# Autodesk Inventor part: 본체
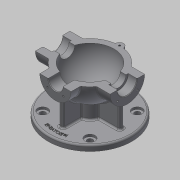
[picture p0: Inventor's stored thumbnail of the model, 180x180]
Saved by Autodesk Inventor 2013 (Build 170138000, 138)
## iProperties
Created: 2015-12
Part Number: 본체
Material: 일반
Document SubType Name: Modeling
Designer: mduedu
Density: 1 g/cm^3
Mass: 407.074 g
Surface Area: 905.391 cm^2
Volume: 407.074 cm^3
Author: mduedu
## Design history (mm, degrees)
sketch "스케치1"
  geometry: L1 (-53, 0)-(53, 0); A1 r 53 centre (0, 0) between (53, 0) and (-53, 0); 2 further points
  constraints: 2 coincident, 2 end point, 2 point on circle, 1 centre point, 1 horizontal, 1 midpoint
  dimensions: "d0" = 53 radius of A1
revolve "회전1" sketch "스케치1" stored, may be unused: angle "d2" = 90 deg
feature "쉘1" dims "d11" = 10
node "작업 평면1"
sketch "스케치2"
  geometry: C1 r 31 at (0, 0); 1 further point
  constraints: 1 centre point, 1 coincident
  dimensions: "d4" = 62 diameter of C1
extrude "돌출1" join sketch "스케치2" stored distance "d5" = 10; taper "d6" = 0 deg
node "작업 평면2"
sketch "스케치3"
  geometry: C1 r 28 at (0, 0); 1 further point
  constraints: 1 centre point, 1 coincident
  dimensions: "d8" = 56 diameter of C1
extrude "돌출2" join sketch "스케치3" stored distance "d9" = 10; taper "d10" = 0 deg
hole "구멍1" diameter "d14" = 35; stored, may be unused: countersink angle "d18" = 90 deg, drill point angle "d20" = 0 deg; dims "d12" = 10, "d13" = 10, "d15" = 6, "d16" = 4, "d17" = 2, "d19" = 16
hole "구멍2" diameter "d23" = 27; stored, may be unused: countersink angle "d27" = 90 deg, drill point angle "d29" = 0 deg; dims "d21" = 10, "d22" = 10, "d24" = 6, "d25" = 4, "d26" = 2, "d28" = 16
fillet "모깎기1" dims "d30" = 0.3
hole "구멍3" diameter "d33" = 26; stored, may be unused: countersink angle "d37" = 90 deg, drill point angle "d39" = 0 deg; dims "d31" = 10, "d32" = 10, "d34" = 6, "d35" = 4, "d36" = 2, "d38" = 16
chamfer "모따기1" distance "d40" = 1; stored, may be unused: second distance "d41" = 2, angle "d42" = 45 deg
sketch "스케치4"
  geometry: L1 (0, 0)-(0, -25); L2 (0, 0)-(-17.678, -17.678); A1 r 25 centre (0, 0) between (-17.678, -17.678) and (0, -25); 1 further point
  constraints: 4 end point, 2 point on circle, 1 centre point, 1 coincident, 1 vertical
  dimensions: "d43" = 50 diameter of A1; "d47" = 45 deg angle of L1 L2
hole "구멍4" sketch "스케치4" at (-17.678, -17.678) diameter "d49" = 3.242; stored, may be unused: countersink angle "d53" = 90 deg, drill point angle "d55" = 118 deg; dims "d50" = 11, "d51" = 4, "d52" = 2, "d54" = 13
sketch "스케치5"
  geometry: L1 (0, 0)-(0, -20); L2 (0, 0)-(-14.142, -14.142); A1 r 20 centre (0, 0) between (0, -20) and (-14.142, -14.142); 2 further points
  constraints: 4 end point, 2 coincident, 2 point on circle, 1 centre point, 1 vertical
  dimensions: "d59" = 40 diameter of A1; "d65" = 45 deg angle of L1 L2
hole "구멍5" sketch "스케치5" at (-14.142, -14.142) diameter "d67" = 3.242; stored, may be unused: countersink angle "d71" = 90 deg, drill point angle "d73" = 118 deg; dims "d68" = 8, "d69" = 4, "d70" = 2, "d72" = 10
node "작업 평면3"
sketch "스케치6"
  geometry: C1 r 75 at (0, 0); 1 further point
  constraints: 1 centre point, 1 coincident
  dimensions: "d78" = 150 diameter of C1
extrude "돌출3" join sketch "스케치6" distance "d80" = 10; taper "d81" = 0 deg
sketch "스케치7"
  geometry: C1 r 20 at (0, 0); 1 further point
  constraints: 1 centre point, 1 coincident
  dimensions: "d82" = 40 diameter of C1
extrude "돌출4" join sketch "스케치7" stored distance "d84" = 10; taper "d85" = 0 deg
sketch "스케치8"
  geometry: 2 further points
  constraints: 1 coincident
hole "구멍6" sketch "스케치8" at (0, 0) diameter "d86" = 20; stored, may be unused: countersink angle "d90" = 90 deg, drill point angle "d92" = 118 deg; dims "d87" = 7, "d88" = 40, "d89" = 5, "d91" = 10
fillet "모깎기2" dims "d93" = 0.3
sketch "스케치9"
  geometry: L1 (-67, -18.5)-(-66, -17.5) reference; L2 (-66, -17.5)-(-51.3, -17.5) reference; L3 (-51, -17.2)-(-51, -13.5) reference; L4 (-51, -13.5)-(-40.826, -13.5) reference; L5 (-10, -41.821)-(-10, -80) reference; L6 (-10, -80)-(-19.7, -80) reference; L7 (-20, -80.3)-(-20, -85) reference; L8 (-20, -85)-(-75, -85) reference; L9 (-75, -85)-(-75, -75) reference; L10 (-75, -75)-(-20, -75) reference; L11 (-20, -75)-(-20, -49.082) reference; L12 (-42.988, -31)-(-67, -31) reference; L13 (-67, -31)-(-67, -18.5) reference; L14 (66, -17.5)-(67, -18.5) reference; L15 (67, -18.5)-(67, -31) reference; L16 (67, -31)-(42.988, -31) reference; L17 (20, -49.082)-(20, -75) reference; L18 (20, -75)-(75, -75) reference; L19 (75, -75)-(75, -85) reference; L20 (75, -85)-(20, -85) reference; L21 (20, -85)-(20, -80.3) reference; L22 (19.7, -80)-(10, -80) reference; L23 (10, -80)-(10, -41.821) reference; L24 (40.826, -13.5)-(51, -13.5) reference; L25 (51, -13.5)-(51, -17.2) reference; L26 (51.3, -17.5)-(66, -17.5) reference; L27 (67, 18.5)-(66, 17.5) reference; L28 (66, 17.5)-(51.3, 17.5) reference; L29 (51, 17.2)-(51, 13.5) reference; L30 (51, 13.5)-(40.826, 13.5) reference; L31 (-40.826, 13.5)-(-51, 13.5) reference; L32 (-51, 13.5)-(-51, 17.2) reference; L33 (-51.3, 17.5)-(-66, 17.5) reference; L34 (-66, 17.5)-(-67, 18.5) reference; L35 (-67, 18.5)-(-67, 31) reference; L36 (-67, 31)-(-42.988, 31) reference; L37 (42.988, 31)-(67, 31) reference; L38 (67, 31)-(67, 18.5) reference; L39 (-57, -31)-(-57, -75); A1 r 0.3 centre (-51.3, -17.2) between (-51.3, -17.5) and (-51, -17.2) reference; A2 r 43 centre (0, 0) between (-40.826, -13.5) and (-10, -41.821) reference; A3 r 0.3 centre (-19.7, -80.3) between (-19.7, -80) and (-20, -80.3) reference; A4 r 53 centre (0, 0) between (-42.988, -31) and (-20, -49.082) reference; A5 r 53 centre (0, 0) between (20, -49.082) and (42.988, -31) reference; A6 r 0.3 centre (19.7, -80.3) between (20, -80.3) and (19.7, -80) reference; A7 r 43 centre (0, 0) between (10, -41.821) and (40.826, -13.5) reference; A8 r 0.3 centre (51.3, -17.2) between (51, -17.2) and (51.3, -17.5) reference; A9 r 0.3 centre (51.3, 17.2) between (51.3, 17.5) and (51, 17.2) reference; A10 r 43 centre (0, 0) between (40.826, 13.5) and (-40.826, 13.5) reference; A11 r 0.3 centre (-51.3, 17.2) between (-51, 17.2) and (-51.3, 17.5) reference; A12 r 53 centre (0, 0) between (42.988, 31) and (-42.988, 31) reference; 1 further point
  constraints: 2 end point, 2 point on line, 1 perpendicular
  dimensions: "d151" = 10 distance between parallel lines of L39 L13
feature "리브1" sketch "스케치9" dims "d96" = 1, "d97" = 8, "d98" = 0, "d99" = 0, "d100" = 1, "d101" = 1
sketch "스케치14"
  geometry: L1 (-14, 62)-(-13, 61) reference; L2 (-13, 61)-(-13, 40.988) reference; L3 (-41.821, 10)-(-80, 10) reference; L4 (-80, 10)-(-80, 19.7) reference; L5 (-80.3, 20)-(-85, 20) reference; L6 (-85, 20)-(-85, 75) reference; L7 (-85, 75)-(-75, 75) reference; L8 (-75, 75)-(-75, 20) reference; L9 (-75, 20)-(-49.082, 20) reference; L10 (-28, 45)-(-28, 62) reference; L11 (-28, 62)-(-14, 62) reference; L12 (13, 61)-(14, 62) reference; L13 (14, 62)-(28, 62) reference; L14 (28, 62)-(28, 45) reference; L15 (-49.082, -20)-(-75, -20) reference; L16 (-75, -20)-(-75, -75) reference; L17 (-75, -75)-(-85, -75) reference; L18 (-85, -75)-(-85, -20) reference; L19 (-85, -20)-(-80.3, -20) reference; L20 (-80, -19.7)-(-80, -10) reference; L21 (-80, -10)-(-41.821, -10) reference; L22 (13, 40.988)-(13, 61) reference; L23 (-28, 52)-(-75, 52); A1 r 43 centre (0, 0) between (-13, 40.988) and (-41.821, 10) reference; A2 r 0.3 centre (-80.3, 19.7) between (-80, 19.7) and (-80.3, 20) reference; A3 r 53 centre (0, 0) between (-28, 45) and (-49.082, 20) reference; A4 r 53 centre (0, 0) between (0, -53) and (28, 45) reference; A5 r 53 centre (0, 0) between (-49.082, -20) and (0, -53) reference; A6 r 0.3 centre (-80.3, -19.7) between (-80.3, -20) and (-80, -19.7) reference; A7 r 43 centre (0, 0) between (-41.821, -10) and (0, -43) reference; A8 r 43 centre (0, 0) between (0, -43) and (13, 40.988) reference; 1 further point
  constraints: 2 end point, 2 point on line, 1 perpendicular
  dimensions: "d152" = 10 distance between parallel lines of L23 L11
feature "리브2" sketch "스케치14" dims "d153" = 1, "d154" = 8, "d155" = 0, "d156" = 0, "d157" = 1, "d158" = 1
sketch "스케치10"
  geometry: L1 (0, 0)-(0, -60); L2 (0, 0)-(-42.426, -42.426); A1 r 60 centre (0, 0) between (0, -60) and (-42.426, -42.426); 2 further points
  constraints: 4 end point, 2 coincident, 2 point on circle, 1 centre point, 1 vertical
  dimensions: "d105" = 120 diameter of A1; "d107" = 45 deg angle of L1 L2
hole "구멍7" sketch "스케치10" at (-42.426, -42.426) diameter "d109" = 10; stored, may be unused: countersink angle "d113" = 90 deg, drill point angle "d115" = 118 deg; dims "d110" = 7, "d111" = 18, "d112" = 4, "d114" = 10
fillet "모깎기3" dims "d120" = 3
fillet "모깎기4" dims "d121" = 3, "d122" = 3
fillet "모깎기5" dims "d123" = 3
fillet "모깎기6" dims "d124" = 3
sketch "스케치11"
  geometry: C1 r 75 at (0, 0) reference; C2 r 65 at (0, 0)
  constraints: 1 centre point, 1 coincident, 1 other
  dimensions: "d161" = 130 diameter of C2
feature "엠보싱1" sketch "스케치11" dims "d11" = 10, "d125" = 0.5, "d126" = 0
sketch "스케치12"
  geometry: L1 (0, 100)-(0, -100); L2 (0, 100)-(100, 100); L3 (100, 100)-(100, -100); L4 (100, -100)-(0, -100); 2 further points
  constraints: 8 end point, 3 perpendicular, 1 coincident, 1 midpoint, 1 vertical
  dimensions: "d127" = 200 distance of L2.end L3.end; "d129" = 100 distance between parallel lines of L1 L3
extrude "돌출5" cut sketch "스케치12" stored distance "d130" = 10; taper "d131" = 0 deg
sketch "스케치13"
  geometry: C1 r 7 at (0, 53); A1 r 53 centre (0, 0) between (42.113, 32.179) and (-42.113, 32.179) reference; 1 further point
  constraints: 1 centre point, 1 point on circle
  dimensions: "d132" = 14 diameter of C1
extrude "돌출6" join sketch "스케치13" distance "d134" = 15; taper "d135" = 0 deg
hole "구멍8" diameter "d139" = 3.242; stored, may be unused: countersink angle "d143" = 90 deg, drill point angle "d145" = 118 deg; dims "d140" = 8, "d141" = 4, "d142" = 2, "d144" = 10, "d148" = 10, "d149" = 10
fillet "모깎기7" dims "d146" = 3
fillet "모깎기8" dims "d147" = 3
node "솔리드1"
mirror "대칭1"
mirror "대칭2"
pattern_circular "원형 패턴1" dims angle "d57" = 360 deg
mirror "대칭3"
pattern_circular "원형 패턴2" dims angle "d75" = 360 deg
mirror "대칭4"
pattern_circular "원형 패턴4" dims angle "d118" = 360 deg
node "절단 모서리 투영1"
node "절단 모서리 투영2"
other parameters: "d3" = 67, "d7" = 62, "d77" = -85
